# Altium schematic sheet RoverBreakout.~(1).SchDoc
size A
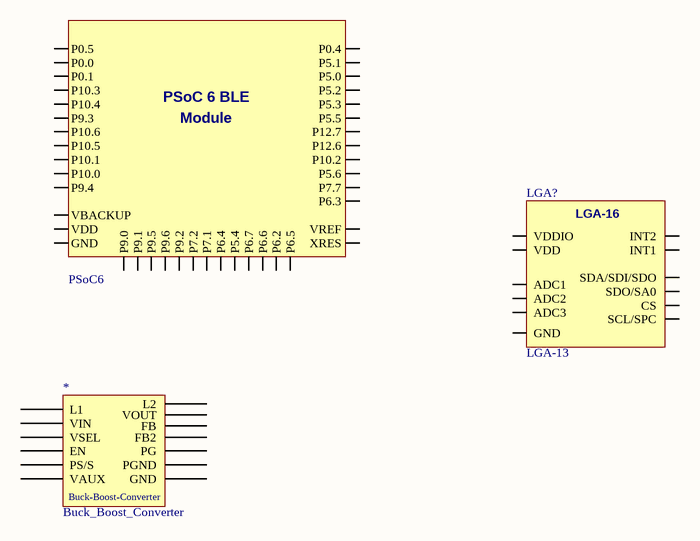
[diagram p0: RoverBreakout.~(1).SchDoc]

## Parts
*  Buck_Boost_Converter  [Buck_Boost_Converter]
LGA?  LGA-13  [LIS3DH]
PSoC6  Micro-PSoC6-Module  [MICRO-PSOC6-MODULE]  (value not drawn)

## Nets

Not connected (* = marked no-connect by the designer): * EN FB FB2 GND L1 L2 PG PGND PS/S VAUX VIN VOUT VSEL; LGA? ADC1 ADC2 ADC3 CS GND INT1 INT2 SCL/SPC SDA/SDI/SDO SDO/SA0 VDD VDDIO; PSoC6 GND P0.0 P0.1 P0.4 P0.5 P5.0 P5.1 P5.2 P5.3 P5.4 P5.5 P5.6 P6.2 P6.3 P6.4 P6.5 P6.6 P6.7 P7.1 P7.2 P7.7 P9.0 P9.1 P9.2 P9.3 P9.4 P9.5 P9.6 P10.0 P10.1 P10.2 P10.3 P10.4 P10.5 P10.6 P12.6 P12.7 VBACKUP VDD VREF XRES

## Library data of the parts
PSoC6 = Micro-PSoC6-Module: PSoC 6 BLE Module; Manufacturer: Cypress; Manufacturer Part Number: CYBLE-416045-02; Through Hole (y/n): N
